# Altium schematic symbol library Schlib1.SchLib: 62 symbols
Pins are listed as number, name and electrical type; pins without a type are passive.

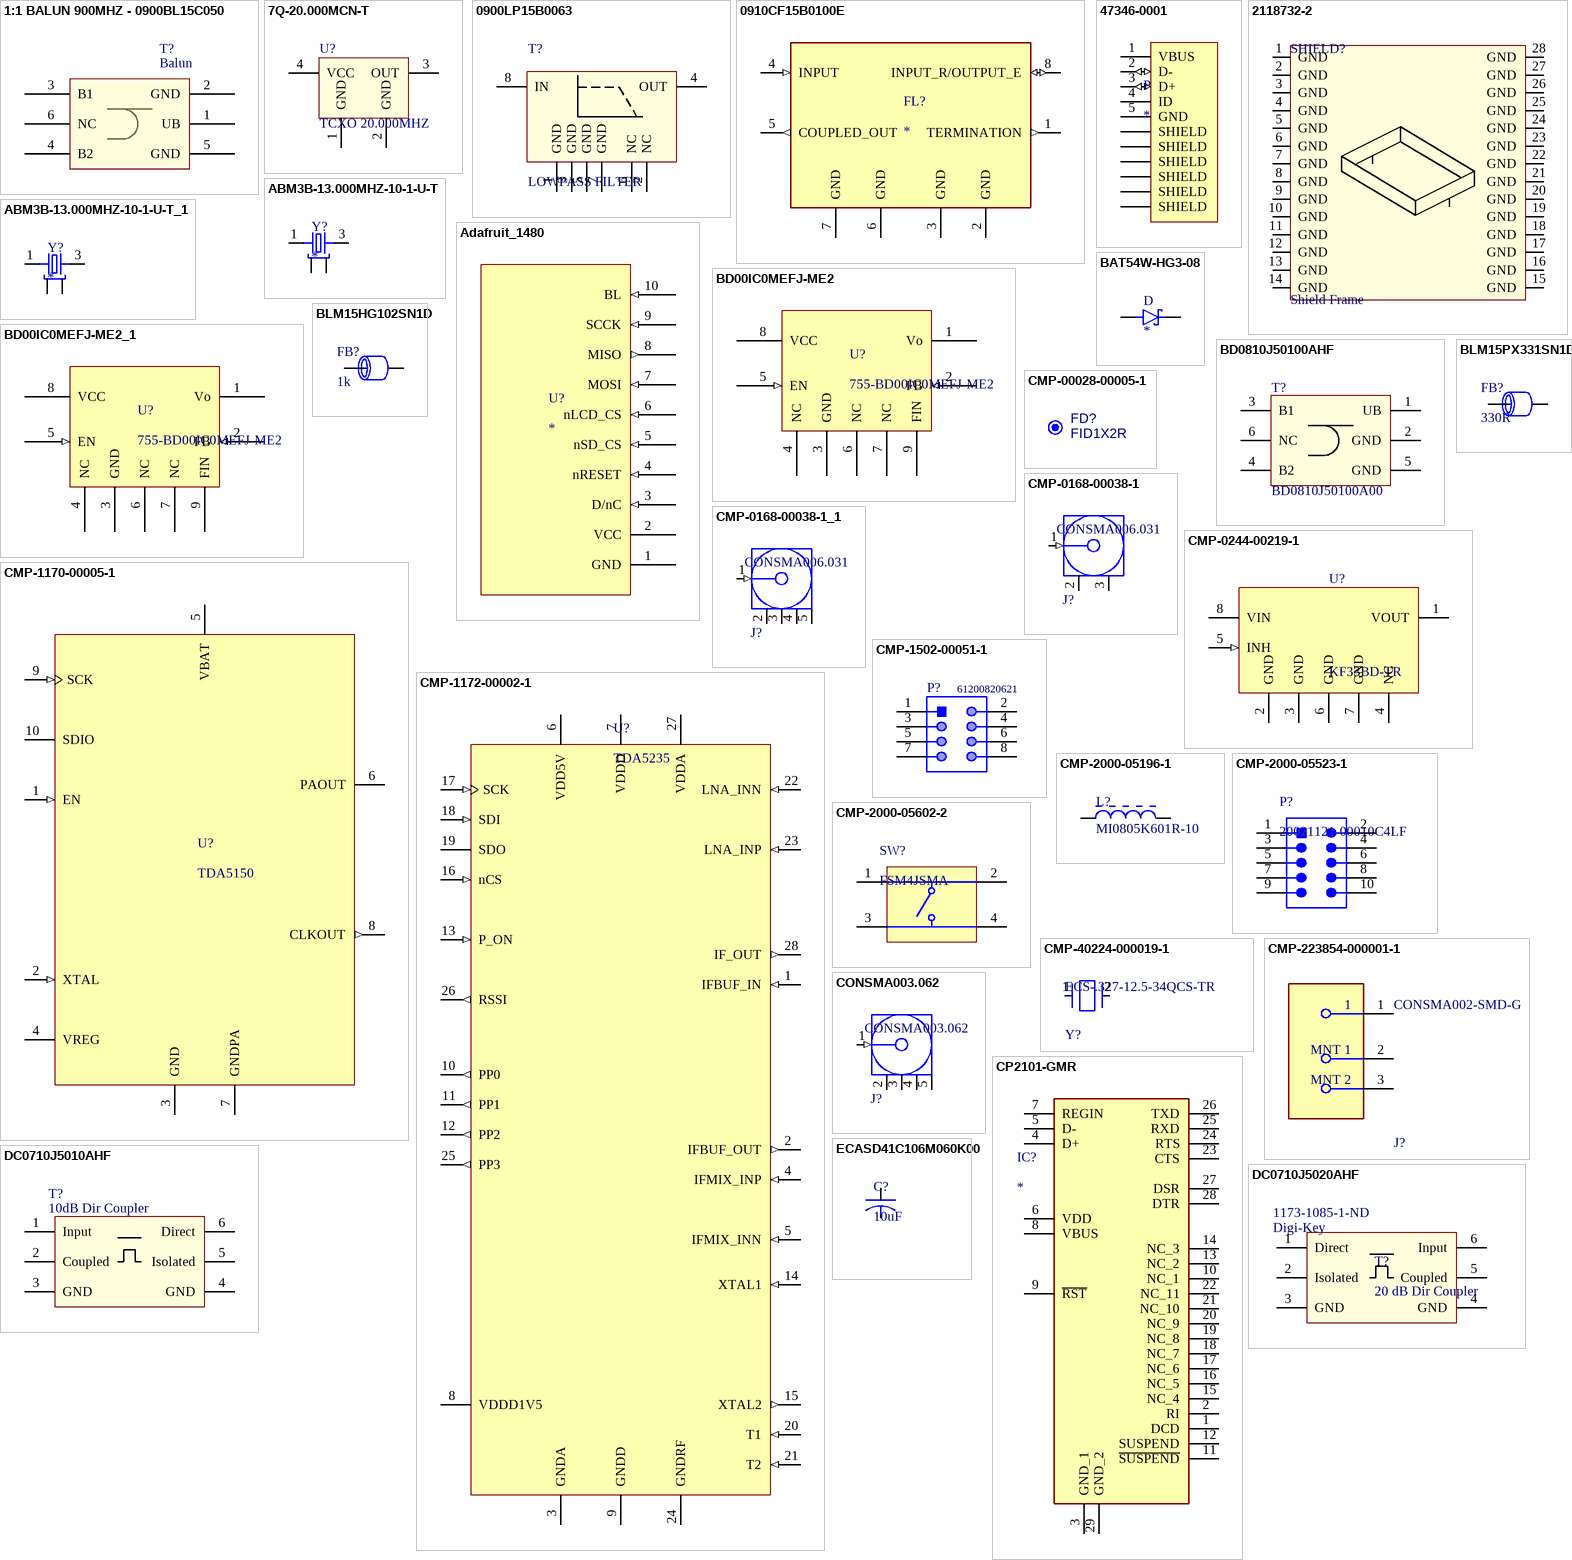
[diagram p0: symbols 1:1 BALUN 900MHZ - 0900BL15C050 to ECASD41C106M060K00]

## 1:1 BALUN 900MHZ - 0900BL15C050
designator T?, comment Balun
1:1 BALUN- 900MHZ 50/50 Ohm; Manufacturer: Johanson Technology Inc; Manufacturer Part Number: 0900BL15C050E; Component_Description: BALUN GSM/DCS/PCS/CDMA 900MHZ; Frequency Range: 800 ~ 1000MHz; Phase Difference: 180° ±10; Insertion Loss (Max): 1.2dB; Return Loss (Min): 9.5dB
footprint JTI-0900BL15C050 (900 MHz Balun 1:1)
pins: 1 UB, 2 GND, 3 B1, 4 B2, 5 GND, 6 NC

## 7Q-20.000MCN-T
designator U?, comment TCXO 20.000MHZ
OSC TCXO 20.000MHZ CLPD SNWV SMD; Manufacturer: Taitien; Manufacturer Part Number: TXEAADSANF-20.000000; Output: Clipped Sine Wave; Voltage - Supply: 2.8 V ~ 3.3 V; Frequency Stability: ±500ppb; Current - Supply (Max): 2mA
footprint 7Q-20.000MCN-T (Footprint not found)
footprint TY_TYPE_2.5x2.0mm (TCXO package Taitien TY type)
pins: 1 GND, 2 GND, 3 OUT, 4 VCC

## 0900LP15B0063
designator T?, comment LOWPASS FILTER
FILTER LOWPASS 863-960MHZ; Manufacturer: Johanson Technology Inc.; Manufacturer Part Number: 0900LP15B0063E
footprint JTI-0900LP15B0063 (900 MHz Low Pass Filter)
pins: 1 GND, 2 NC, 3 GND, 4 OUT, 5 GND, 6 NC, 7 GND, 8 IN

## 0910CF15B0100E
designator FL?
RF Couplers Coupling 10dB 0.86GHz to 0.96GHz 8-Pin T/R; MP: 0910CF15B0100E
footprint FIL_0910CF15B0100E
pins: 1 TERMINATION (out), 2 GND (power), 3 GND (power), 4 INPUT (in), 5 COUPLED_OUT (out), 6 GND (power), 7 GND (power), 8 INPUT_R/OUTPUT_E (io)

## 47346-0001
designator P
USB - micro B USB 2.0 Receptacle Connector 5 Position Surface Mount, Right Angle; MF: Molex; MP: 47346-0001
footprint MOLEX_47346-0001 (Footprint not found)
pins: 1 VBUS (power), 2 D- (io), 3 D+ (io), 4 ID, 5 GND (power), SH1 SHIELD, SH2 SHIELD, SH3 SHIELD, SH4 SHIELD, SH5 SHIELD, SH6 SHIELD

## 2118732-2
designator SHIELD?, comment Shield Frame
RF Shield 51.1 x 38.4 x 6.5; Manufacturer: TE Connectivity AMP Connectors; Manufacturer Part Number: 2118732-2
footprint RF Shield - 50.8 x 38.1 mm (2118732-2)
pins: 1 GND, 2 GND, 3 GND, 4 GND, 5 GND, 6 GND, 7 GND, 8 GND, 9 GND, 10 GND, 11 GND, 12 GND, 13 GND, 14 GND, 15 GND, 16 GND, 17 GND, 18 GND, 19 GND, 20 GND, 21 GND, 22 GND, 23 GND, 24 GND, 25 GND, 26 GND, 27 GND, 28 GND

## ABM3B-13.000MHZ-10-1-U-T
designator Y?
Ceramic SMD Crystal; MP: ABM3B-13.000MHZ-10-1-U-T
footprint OSCCC500X320X110-4N
pins: 1, 2 GND, 3, 4 GND

## ABM3B-13.000MHZ-10-1-U-T_1
designator Y?
Ceramic SMD Crystal; MP: ABM3B-13.000MHZ-10-1-U-T
footprint OSCCC500X320X110-4N
pins: 1, 2 GND, 3, 4 GND

## Adafruit_1480
designator U?
LCD Module Adafruit 1480, SPI 320x240p 2.2"
pins: 1 GND (power), 2 VCC (power), 3 D/nC (in), 4 nRESET (in), 5 nSD_CS (in), 6 nLCD_CS (in), 7 MOSI (in), 8 MISO (out), 9 SCCK (in), 10 BL (in)

## BAT54W-HG3-08
designator D
Schottky Diodes & Rectifiers 30V Zener SKY DIODE SOD-123; MP: BAT54W-HG3-08; MF: Vishay Semiconductors
footprint SOD3715X135N
pins: A, K

## BD00IC0MEFJ-ME2
designator U?, comment 755-BD00IC0MEFJ-ME2
Régulateurs de tension LDO IC Pwr Linear Reg Single Output LDO
footprint HTSOP-J8 (HTSOP, 8-Leads, Body 4.90x3.90mm, Pitch 1.27mm, Thermal Pad 3.20x2.40mm, IPC Medium Density)
pins: 1 Vo (power), 2 FB (in), 3 GND (power), 4 NC (power), 5 EN (in), 6 NC (power), 7 NC (power), 8 VCC (power), 9 FIN (power)

## BD00IC0MEFJ-ME2_1
designator U?, comment 755-BD00IC0MEFJ-ME2
Régulateurs de tension LDO IC Pwr Linear Reg Single Output LDO
footprint HTSOP-J8 (HTSOP, 8-Leads, Body 4.90x3.90mm, Pitch 1.27mm, Thermal Pad 3.20x2.40mm, IPC Medium Density)
pins: 1 Vo (power), 2 FB (in), 3 GND (power), 4 NC (power), 5 EN (in), 6 NC (power), 7 NC (power), 8 VCC (power), 9 FIN (power)

## BD0810J50100AHF
designator T?, comment BD0810J50100A00
XFRMR BALUN RF 800-1000MHZ 0805; Manufacturer: Anaren; Manufacturer Part Number: BD0810J50100AHF; Frequency Range: 800MHz ~ 1GHz; Impedance - Unbalanced/Balanced: 50 / 100 Ohm; Phase Difference: 1°; Insertion Loss (Max): 0.95dB; Return Loss (Min): 13dB
footprint BD0810J50100AHF (RF Balun 800MHz ~ 1GHz 50 / 100 Ohm 0805)
pins: 1 UB, 2 GND, 3 B1, 4 B2, 5 GND, 6 NC

## BLM15HG102SN1D
designator FB?, comment 1k
FERRITE BEAD 1 KOHM 0402 1LN; Manufacturer: Murata Electronics North America; Manufacturer Part Number: BLM15HG102SN1D; Filter Type: Signal Line; Number of Lines: 1; Impedance @ Frequency: 1 kOhm @ 100MHz; Current Rating (Max): 250mA; DC Resistance (DCR) (Max): 1.1 Ohm
footprint L0402-RF
pins: 1, 2

## BLM15PX331SN1D
designator FB?, comment 330R
FERRITE BEAD 330 OHM 0402 1LN; Manufacturer: Murata Electronics North America; Manufacturer Part Number: BLM15PX331SN1D; Filter Type: Power Line; Current Rating (Max): 1.2A; DC Resistance (DCR) (Max): 150 mOhm
footprint FB0402-RF (Ferrite Bead)
pins: 1, 2

## CMP-00028-00005-1
designator FD?, comment FID1X2R  (no BOM)
Fiducial - Round 1x2mm
footprint FID1X2R (Fiducial - Round 1x2mm)
footprint FID1X2R (Fiducial - Round 1x2mm)

## CMP-0168-00038-1
designator J?, comment CONSMA006.031
SMA Female Edge Multi-Mount Connector for 0.031" Thick Board; PCB_Layout: Pads complies with manufacturer's recommendation.
footprint CON-SMA-MM031 (Connector, SMA Female Edge Multi-Mount for 0.031" Thick Board, 5-Lead, Body Dia. 7.9mm)
footprint FP-U_FL-R-SMT-1_10-MFG
pins: 1 Signal (in) "Signal Pin", 2 GND (power), 3 GND (power)

## CMP-0168-00038-1_1
designator J?, comment CONSMA006.031
SMA Female Edge Multi-Mount Connector for 0.031" Thick Board; PCB_Layout: Pads complies with manufacturer's recommendation.
footprint CON-SMA-MM031 (Connector, SMA Female Edge Multi-Mount for 0.031" Thick Board, 5-Lead, Body Dia. 7.9mm)
pins: 1 Signal (in) "Signal Pin", 2 GND (power), 3 GND (power), 4 GND (power), 5 GND (power)

## CMP-0244-00219-1
designator U?, comment KF33BD-TR
Very Low Drop Voltage Regulators with Inhibit, 3.3V, 8-Pin SO, Tape and Reel
footprint SO8_L (SOIC, 8-Leads, Body 4.9x3.9mm, Pitch 1.27mm, IPC High Density)
footprint SO8_N (SOIC, 8-Leads, Body 4.9x3.9mm, Pitch 1.27mm, IPC Medium Density)
footprint SO8_M (SOIC, 8-Leads, Body 4.9x3.9mm, Pitch 1.27mm, IPC Low Density)
pins: 1 VOUT (power), 2 GND (power), 3 GND (power), 4 NC, 5 INH (in), 6 GND (power), 7 GND (power), 8 VIN (power)

## CMP-1170-00005-1
designator U?, comment TDA5150
Multichannel / Multiband Transmitter, -40 to 85 degC, PG-TSSOP-10, Green; Manufacturer: Infineon; Transmit Power (at 3V): 5 dBm, 8 dBm, 10 dBm; Modulation Type: ASK / FSK; Group: SmartLEWIS TX to Multi-Channel Transmitter; Green: yes; Frequency Band: 315 MHz, 434 MHz, 868 MHz, 915 MHz
footprint INF-PG-TSSOP-10_N (SOP, 10-Leads, Body 3x3 mm, Pitch 0.5 mm, IPC Medium Density)
footprint INF-PG-TSSOP-10_M (SOP, 10-Leads, Body 3x3 mm, Pitch 0.5 mm, IPC Low Density)
footprint INF-PG-TSSOP-10_L (SOP, 10-Leads, Body 3x3 mm, Pitch 0.5 mm, IPC High Density)
pins: 1 EN (in) "Clock 3-wire bus", 2 XTAL (in) "Crystal Oscillator (Analog input)", 3 GND (power) "Power supply ground", 4 VREG (power) "Voltage Regulator output", 5 VBAT (power) "Power supply (+)", 6 PAOUT (oc) "RF Power  Amplifier Output  (open drain)", 7 GNDPA (power) "RF Power  Amplifier Ground return", 8 CLKOUT (out) "Programmable Divided Clock", 9 SCK (in) "Clock 3-wire bus", 10 SDIO (hiz) "Data 3-wire bus"

## CMP-1172-00002-1
designator U?, comment TDA5235
Enhanced Sensitivity Double-Configuration Receiver with Digital Baseband Processing, -40 to 105 degC, PG-TSSOP-28, Green; Manufacturer: Infineon; Digital Baseband / Autonomous RX: yes; Frequency Band: 315 MHz, 434 MHz, 868 MHz, 915 MHz; Modulation Type: ASK / FSK; Group: SmartLEWIS RX+ to High Sensitivity Receiver with Digital Baseband Processing; Channel Requirements per Band: Single-Channel
footprint INF-PG-TSSOP-28_L (SOP, 28-Leads, Body 9.7x4.4 mm, Pitch 0.65 mm, IPC High Density)
footprint INF-PG-TSSOP-28_N (SOP, 28-Leads, Body 9.7x4.4 mm, Pitch 0.65 mm, IPC Medium Density)
footprint INF-PG-TSSOP-28_M (SOP, 28-Leads, Body 9.7x4.4 mm, Pitch 0.65 mm, IPC Low Density)
pins: 1 IFBUF_IN (in) "Analog input IF Buffer input Note: Input is biased at VDDA/2", 2 IFBUF_OUT (out) "Analog output IF Buffer output", 3 GNDA (power) "Analog ground", 4 IFMIX_INP (in) "Analog input + IF mixer input Note: Input is biased at VDDA/2", 5 IFMIX_INN (in) "Analog input. - IF mixer input", 6 VDD5V (power) "Analog input 5 Volt supply input", 7 VDDD (power) "Analog input digital supply input", 8 VDDD1V5 (power) "Analog output 1.5 Volt voltage regulator", 9 GNDD (power) "Digital ground", 10 PP0 (out) "Digital output CLK_OUT, RX_RUN, NINT, LOW, HIGH, DATA and DATA_MATCHFIL are programmable via a SFR (Special Function Register), default = CLK_OUT", 11 PP1 (out) "Digital output CLK_OUT, RX_RUN, NINT, LOW, HIGH, DATA and DATA_MATCHFIL are programmable via a SFR, default = DATA", 12 PP2 (out) "Digital output CLK_OUT, RX_RUN, NINT, LOW, HIGH, DATA and DATA_MATCHFIL are programmable via a SFR, default = NINT", 13 P_ON (in) "Digital input power-on reset", 14 XTAL1 (in) "Analog input crystal oscillator input", 15 XTAL2 (out) "Analog output crystal oscillator output", 16 nCS (in) "Digital input SPI enable", 17 SCK (in) "Digital input SPI clock", 18 SDI (in) "Digital input SPI data in", 19 SDO (hiz) "Digital output SPI data out", 20 T1 (in) "Digital input, connect to Digital Ground", 21 T2 (in) "Digital input, connect to Digital Ground", 22 LNA_INN (in) "Analog input - RF input", 23 LNA_INP (in) "Analog input + RF input", 24 GNDRF (power) "RF analog ground", 25 PP3 (out) "Digital output RX_RUN, NINT, LOW, HIGH, DATA and DATA_MATCHFIL are programmable via a SFR, default = RX_RUN", 26 RSSI (out) "Analog output analog RSSI output/ analog test pin ANA_TST", 27 VDDA (power) "Analog input Analog supply", 28 IF_OUT (out) "Analog output IF output"

## CMP-1502-00051-1
designator P?, comment 61200820621
Male Box Header WR-BHD, SMT, Vertical, pitch 2.54 mm, 8 pins; Manufacturer: Wurth Elektronik; Withstanding Voltage: 500VAC; Pin Number: 8; Pitch: 2.54mm; Contact Resistance: 20mOhm; Working Voltage: 250VAC
footprint 61200820621 (8 pins, SMT, straight, gold plating)
pins: 1, 2, 3, 4, 5, 6, 7, 8

## CMP-2000-05196-1
designator L?, comment MI0805K601R-10
Chip Bead for Power Filtering, 1500 mA, 600 Ohm, -40 to 125 degC, 0805 (2012 Metric), RoHS, Tape and Reel; Manufacturer: Laird; Filter Type: PowerLine; Current Rating (Max): 1.5A; Catalog Drawings: (HI,HZ,LI,MI)0805Series_1.10mmMax.Height; Impedance @ Frequency: 600Ohm@100MHz; Number of Lines: 1; DC Resistance (DCR) (Max): 100mOhm; Other Names: 240-2390-1; Kits: 240-2227-ND-KITEMIFERRITEBEADCHIPSMD; Online Catalog: MISeries
footprint LIRD-MI0805K601R-10-2_V (Chip Bead, 2-Leads, Body 2.2 x1.45 mm)
pins: 1, 2

## CMP-2000-05523-1
designator P?, comment 20021121-00010C4LF
Male Header, Pitch 1.27 mm, 2 x 5 Position, Height 4.55 mm, -40 to 85 degC, RoHS, Tape and Reel; Brand: FCI; Mating Post Length: 3.05mm; Voltage Rating: 125V; Contact resistance Max: 30MOhm; Number of Positions: 10; Pitch: 1.27mm; Current Rating: 1A; Stack Height: 3mm; Mounting Angle: Vertical; Package Version: Rev. J, 03/2013
footprint HDR2X5_SMT (Header, 10-Leads, Body 3.43x6.35mm, Pitch 1.27mm)
pins: 1, 2, 3, 4, 5, 6, 7, 8, 9, 10

## CMP-2000-05602-2
designator SW?, comment FSM4JSMA
Swicth, SPST, 24 V, -35 to 85 degC, 4-Pin SMD, RoHS, Tape and Reel; Manufacturer: TE Connectivity; Switch Travel: 0.25mm; Mechanical Life: 100000Cycles; Contact Current Rating: 50mA; Operating Force: 1.57N; Actuator Material: Polyamide; Contact Resistance: 100mOhm; Voltage Rating: 24V; Illumination Type: Illuminated; Actuator Length: 0.055inch; Max Voltage Rating (DC): 12V; Case\/Package: SMD/SMT
footprint RKB2SJK250SMTRLFS
pins: 1, 2, 3, 4

## CMP-40224-000019-1
designator Y?, comment ECS-.327-12.5-34QCS-TR
CRYSTAL 32.768KHZ 12.5PF SMD; ESR (Equivalent Series Resistance): 80kR; Frequency Tolerance: 10ppm
footprint FP-ECX-34Q-MFG
pins: 1 In/Out (io), 2 Out/In (io)

## CMP-223854-000001-1
designator J?, comment CONSMA002-SMD-G
CONN SMA RCPT R/A 50 OHM SMD; Manufacturer: Linx Technologies; Impedance: 50Ω; Is Female: yes; Number Of Contacts: 1; Conn Orientation: Right Angle; Shielding: true; Voltage Rating: 1000V; Standoff Height: 0mm; Frequency: 18GHz; Dielectric Material: PTFE
footprint FP-CONSMA002-SMD-G-MFG
pins: 1, 2 MNT 1, 3 MNT 2

## CONSMA003.062
designator J?
SMA Female Edge Multi-Mount Connector for 0.062" Thick Board; PCB_Layout: Pads complies with manufacturer's recommendation.
footprint CON-SMA-MM031 (Connector, SMA Female Edge Multi-Mount for 0.031" Thick Board, 5-Lead, Body Dia. 7.9mm)
footprint LINX_CONSMA003.062
pins: 1 Signal (in) "Signal Pin", 2 GND (power), 3 GND (power), 4 GND (power), 5 GND (power)

## CP2101-GMR
designator IC?
Integrated Circuit; Manufacturer_Name: Silicon Labs; Manufacturer_Part_Number: CP2101-GMR; Description: I/O Controller Interface IC USB to UART Bridge QFN28
footprint QFN50P500X500X100-29N-D
pins: 1 DCD, 2 RI, 3 GND_1, 4 D+, 5 D-, 6 VDD, 7 REGIN, 8 VBUS, 9 ~{RST}, 10 NC_1, 11 ~{SUSPEND}, 12 SUSPEND, 13 NC_2, 14 NC_3, 15 NC_4, 16 NC_5, 17 NC_6, 18 NC_7, 19 NC_8, 20 NC_9, 21 NC_10, 22 NC_11, 23 CTS, 24 RTS, 25 RXD, 26 TXD, 27 DSR, 28 DTR, 29 GND_2

## DC0710J5010AHF
designator T?, comment 10dB Dir Coupler
Directional Coupler; Manufacturer: Anaren; Manufacturer Part Number: DC0710J5010AHF; Coupler Type: Standard; Frequency: 700MHz ~ 1GHz; Coupling Factor: 10.9dB; Insertion Loss: 0.21dB; Power - Max: 2W; Return Loss: 17.5dB
footprint DC0710J5010AHF (Directional Coupler)
pins: 1 Input, 2 Coupled, 3 GND, 4 GND, 5 Isolated, 6 Direct

## DC0710J5020AHF
designator T?, comment 20 dB Dir Coupler  Supplier 1: Digi-Key  Supplier Part Number 1: 1173-1085-1-ND
COUPLER 20DB 700-1000MHZ 0805; Manufacturer: Anaren; Manufacturer Part Number: DC0710J5020AHF; Frequency: 700MHz; Insertion Loss: 0.22dB; Max Power Dissipation: 2W; Return Loss: 21.41dB
footprint DC0710J5010AHF (Directional Coupler)
pins: 1 Direct, 2 Isolated, 3 GND, 4 GND, 5 Coupled, 6 Input

## ECASD41C106M060K00
designator C?, comment 10uF
CAP POLYMER 10UF 20% 16V SMD; Manufacturer: Murata; Manufacturer Part Number: ECASD41C106M060K00; Product Training Modules: Polymer Aluminum Electrolytic Capacitors Using Murata's Polymer Aluminum Capacitors to Replace Tantalum; Catalog Drawings: ECAS Series End_D4 ECAS Series Side; Featured Product: ECAS Series Polymer Aluminum Electrolytic Capacitors; EDA / CAD Models: Download from Accelerated Designs; Capacitance: 10µF; ESR (Equivalent Series Resistance): 60 mOhm @ 100kHz; Lifetime @ Temp.: 1000 Hrs @ 105°C; Polarization: Polar; Ripple Current: 1A; Surface Mount Land Size: 0.287" L x 0.169" W (7.30mm x 4.30mm); Online Catalog: ECAS Series; Other Names: 490-5482-2
footprint 2917(7343) (Chip Capacitor, 2-Leads, Body 7,30x4,30mm, IPC Medium Density)
pins: 1, 2

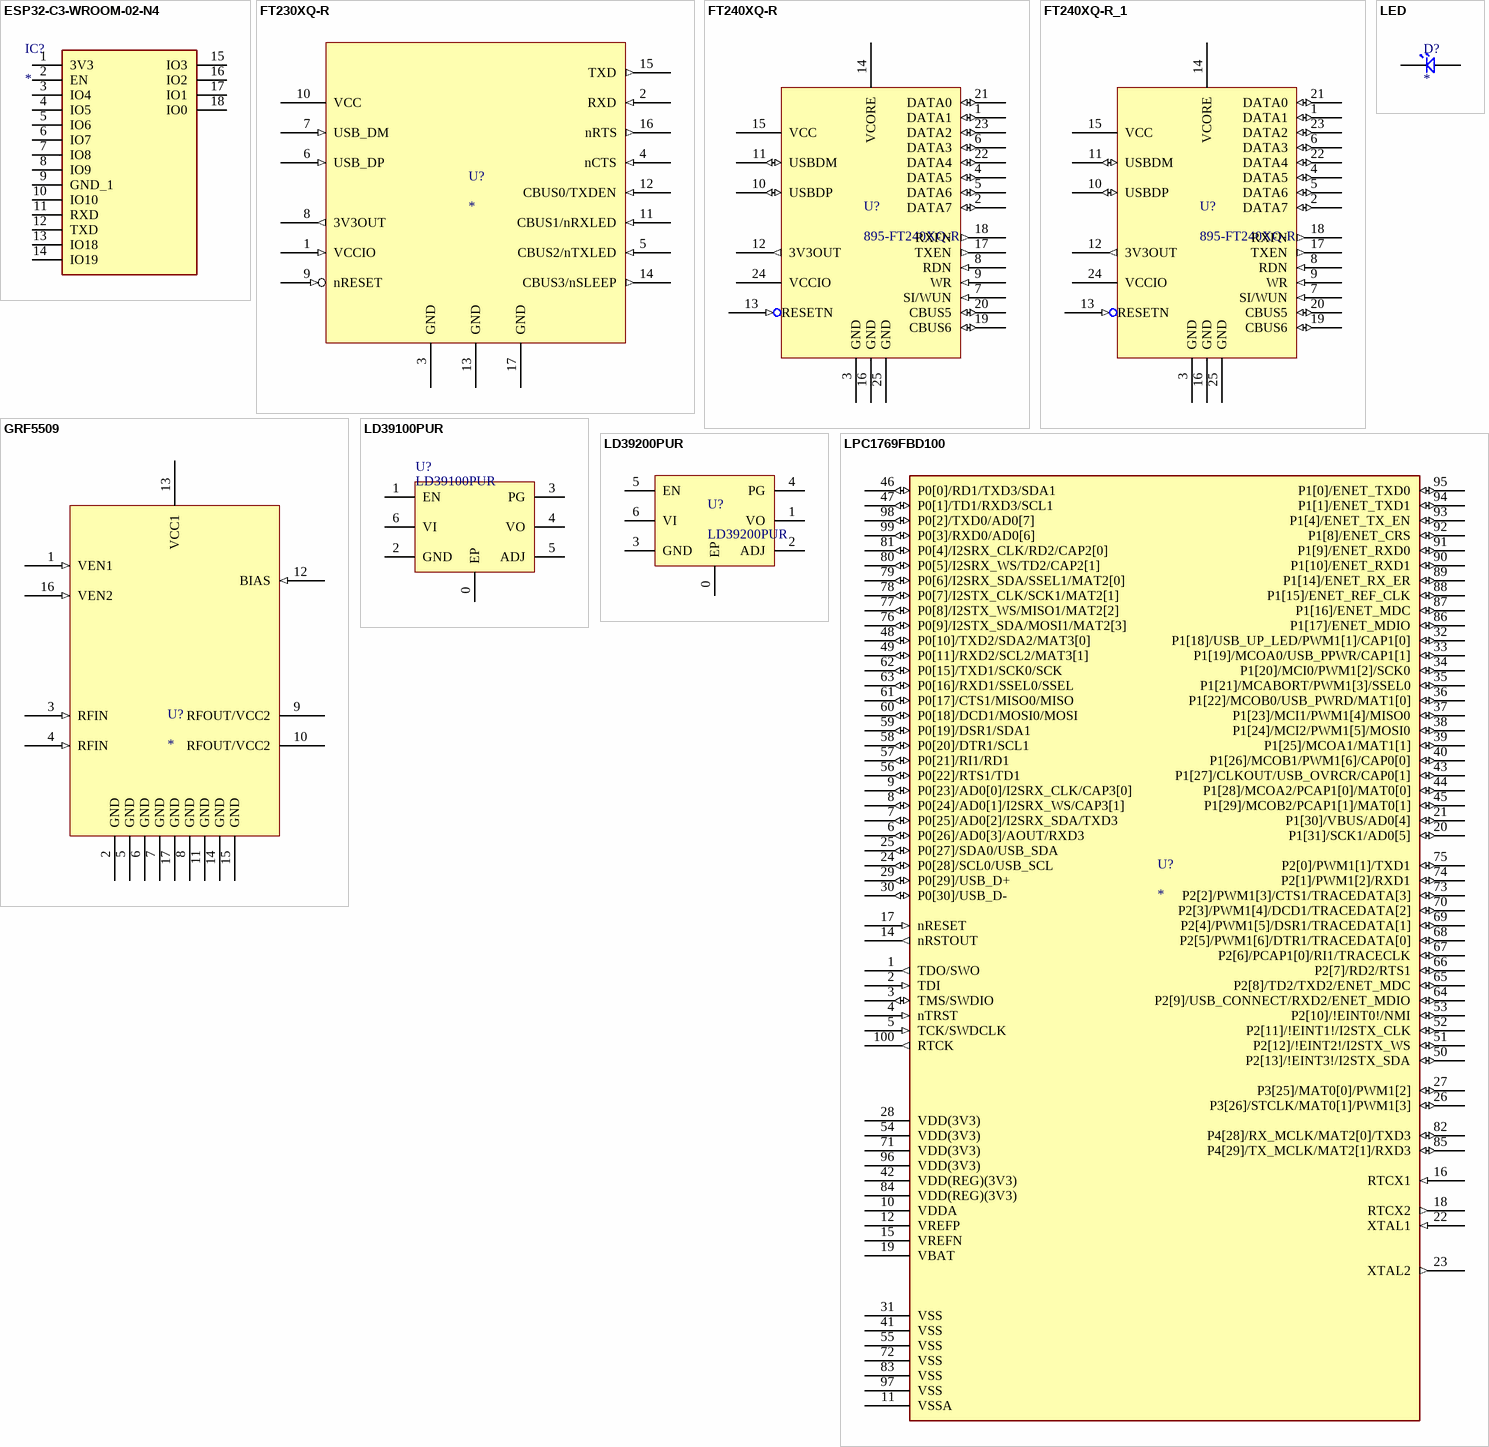
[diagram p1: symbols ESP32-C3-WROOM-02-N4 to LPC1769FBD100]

## ESP32-C3-WROOM-02-N4
designator IC?
Integrated Circuit; Manufacturer_Name: Espressif Systems; Manufacturer_Part_Number: ESP32-C3-WROOM-02-N4
footprint ESP32C3WROOM02N4
pins: 1 3V3, 2 EN, 3 IO4, 4 IO5, 5 IO6, 6 IO7, 7 IO8, 8 IO9, 9 GND_1, 10 IO10, 11 RXD, 12 TXD, 13 IO18, 14 IO19, 15 IO3, 16 IO2, 17 IO1, 18 IO0

## FT230XQ-R
designator U?
USB/UART interface
footprint FP-QFN-16-MFG
pins: 1 VCCIO (in), 2 RXD (in), 3 GND (power), 4 nCTS (in), 5 CBUS2/nTXLED (in), 6 USB_DP (in), 7 USB_DM (in), 8 3V3OUT (out), 9 nRESET (in), 10 VCC (power), 11 CBUS1/nRXLED (in), 12 CBUS0/TXDEN (in), 13 GND (power), 14 CBUS3/nSLEEP (out), 15 TXD (out), 16 nRTS (out), 17 GND (power)

## FT240XQ-R
designator U?, comment 895-FT240XQ-R
Circuit intégré d'interface USB USB to Parallel FIFO IC QFN-24
footprint QFN-24 package - WQFN(X424) pad 114x114 (QFN, 24-Leads, Body 4.00x4.00mm, Pitch 0.50mm, Thermal Pad 2.68x2.68mm, IPC Medium Density)
pins: 1 DATA1 (io), 2 DATA7 (io), 3 GND (power), 4 DATA5 (io), 5 DATA6 (io), 6 DATA3 (io), 7 SI/WUN (in), 8 RDN (in), 9 WR (in), 10 USBDP (io), 11 USBDM (io), 12 3V3OUT (out), 13 RESETN (in), 14 VCORE (power), 15 VCC (power), 16 GND (power), 17 TXEN (out), 18 RXFN (out), 19 CBUS6 (io), 20 CBUS5 (io), 21 DATA0 (io), 22 DATA4 (io), 23 DATA2 (io), 24 VCCIO (power), 25 GND (power)

## FT240XQ-R_1
designator U?, comment 895-FT240XQ-R
Circuit intégré d'interface USB USB to Parallel FIFO IC QFN-24
footprint QFN-24 package - WQFN(X424) pad 114x114 (QFN, 24-Leads, Body 4.00x4.00mm, Pitch 0.50mm, Thermal Pad 2.68x2.68mm, IPC Medium Density)
pins: 1 DATA1 (io), 2 DATA7 (io), 3 GND (power), 4 DATA5 (io), 5 DATA6 (io), 6 DATA3 (io), 7 SI/WUN (in), 8 RDN (in), 9 WR (in), 10 USBDP (io), 11 USBDM (io), 12 3V3OUT (out), 13 RESETN (in), 14 VCORE (power), 15 VCC (power), 16 GND (power), 17 TXEN (out), 18 RXFN (out), 19 CBUS6 (io), 20 CBUS5 (io), 21 DATA0 (io), 22 DATA4 (io), 23 DATA2 (io), 24 VCCIO (power), 25 GND (power)

## GRF5509
designator U?
pins: 1 VEN1 (in), 2 GND (power), 3 RFIN (in), 4 RFIN (in), 5 GND (power), 6 GND (power), 7 GND (power), 8 GND (power), 9 RFOUT/VCC2 (oc), 10 RFOUT/VCC2 (oc), 11 GND (power), 12 BIAS (in), 13 VCC1 (power), 14 GND (power), 15 GND (power), 16 VEN2 (in), 17 GND (power) "PKG BASE"

## LD39100PUR
designator U?
IC REG LDO ADJ 1A 6DFN; Manufacturer: STMicroelectronics; Regulator Topology: Positive Adjustable; Voltage - Output: 0.8 V ~ 4.5 V; Voltage - Dropout (Typical): 0.2V @ 1A; Number of Regulators: 1; Voltage - Input: 1.5 V ~ 5.5 V; Exact Component Match: yes
footprint LD39100PUR (1 A, low quiescent current, low-noise voltage regulator)
pins: 0 EP, 1 EN, 2 GND, 3 PG, 4 VO, 5 ADJ, 6 VI

## LD39200PUR
designator U?
Manufacturer: STMicroelectronics; Capacitance: 10uF; Tolerance: 20%; Dielectric: X6S; Voltage Rating (DC): 10V
footprint LD39200PUR (2 A, low quiescent current, low-noise voltage regulator)
pins: 0 EP, 1 VO, 2 ADJ, 3 GND, 4 PG, 5 EN, 6 VI

## LED
designator D?
footprint LTST-C170KRKT_V (SMD, 2-Leads, Body 2x1.25mm)
pins: A, K

## LPC1769FBD100
designator U?
ARMÂ® CortexÂ®-M3 LPC17xx Microcontroller IC 32-Bit 120MHz 512KB (512K x 8) FLASH 100-LQFP (14x14); MP: LPC1769FBD100; MF: NXP Semiconductors
footprint SOT407-1
pins: 1 TDO/SWO (out), 2 TDI (in), 3 TMS/SWDIO (io), 4 nTRST (in), 5 TCK/SWDCLK (in), 6 P0[26]/AD0[3]/AOUT/RXD3 (io), 7 P0[25]/AD0[2]/I2SRX_SDA/TXD3 (io), 8 P0[24]/AD0[1]/I2SRX_WS/CAP3[1] (io), 9 P0[23]/AD0[0]/I2SRX_CLK/CAP3[0] (io), 10 VDDA (power), 11 VSSA (power), 12 VREFP (power), 14 nRSTOUT (out), 15 VREFN (power), 16 RTCX1 (in), 17 nRESET (in), 18 RTCX2 (out), 19 VBAT (power), 20 P1[31]/SCK1/AD0[5] (io), 21 P1[30]/VBUS/AD0[4] (io), 22 XTAL1 (in), 23 XTAL2 (out), 24 P0[28]/SCL0/USB_SCL (io), 25 P0[27]/SDA0/USB_SDA (io), 26 P3[26]/STCLK/MAT0[1]/PWM1[3] (io), 27 P3[25]/MAT0[0]/PWM1[2] (io), 28 VDD(3V3) (power), 29 P0[29]/USB_D+ (io), 30 P0[30]/USB_D- (io), 31 VSS (power), 32 P1[18]/USB_UP_LED/PWM1[1]/CAP1[0] (io), 33 P1[19]/MCOA0/USB_PPWR/CAP1[1] (io), 34 P1[20]/MCI0/PWM1[2]/SCK0 (io), 35 P1[21]/MCABORT/PWM1[3]/SSEL0 (io), 36 P1[22]/MCOB0/USB_PWRD/MAT1[0] (io), 37 P1[23]/MCI1/PWM1[4]/MISO0 (io), 38 P1[24]/MCI2/PWM1[5]/MOSI0 (io), 39 P1[25]/MCOA1/MAT1[1] (io), 40 P1[26]/MCOB1/PWM1[6]/CAP0[0] (io), 41 VSS (power), 42 VDD(REG)(3V3) (power), 43 P1[27]/CLKOUT/USB_OVRCR/CAP0[1] (io), 44 P1[28]/MCOA2/PCAP1[0]/MAT0[0] (io), 45 P1[29]/MCOB2/PCAP1[1]/MAT0[1] (io), 46 P0[0]/RD1/TXD3/SDA1 (io), 47 P0[1]/TD1/RXD3/SCL1 (io), 48 P0[10]/TXD2/SDA2/MAT3[0] (io), 49 P0[11]/RXD2/SCL2/MAT3[1] (io), 50 P2[13]/!EINT3!/I2STX_SDA (io), 51 P2[12]/!EINT2!/I2STX_WS (io), 52 P2[11]/!EINT1!/I2STX_CLK (io), 53 P2[10]/!EINT0!/NMI (io), 54 VDD(3V3) (power), 55 VSS (power), 56 P0[22]/RTS1/TD1 (io), 57 P0[21]/RI1/RD1 (io), 58 P0[20]/DTR1/SCL1 (io), 59 P0[19]/DSR1/SDA1 (io), 60 P0[18]/DCD1/MOSI0/MOSI (io), 61 P0[17]/CTS1/MISO0/MISO (io), 62 P0[15]/TXD1/SCK0/SCK (io), 63 P0[16]/RXD1/SSEL0/SSEL (io), 64 P2[9]/USB_CONNECT/RXD2/ENET_MDIO (io), 65 P2[8]/TD2/TXD2/ENET_MDC (io), 66 P2[7]/RD2/RTS1 (io), 67 P2[6]/PCAP1[0]/RI1/TRACECLK (io), 68 P2[5]/PWM1[6]/DTR1/TRACEDATA[0] (io), 69 P2[4]/PWM1[5]/DSR1/TRACEDATA[1] (io), 70 P2[3]/PWM1[4]/DCD1/TRACEDATA[2] (io), 71 VDD(3V3) (power), 72 VSS (power), 73 P2[2]/PWM1[3]/CTS1/TRACEDATA[3] (io), 74 P2[1]/PWM1[2]/RXD1 (io), 75 P2[0]/PWM1[1]/TXD1 (io), 76 P0[9]/I2STX_SDA/MOSI1/MAT2[3] (io), 77 P0[8]/I2STX_WS/MISO1/MAT2[2] (io), 78 P0[7]/I2STX_CLK/SCK1/MAT2[1] (io), 79 P0[6]/I2SRX_SDA/SSEL1/MAT2[0] (io), 80 P0[5]/I2SRX_WS/TD2/CAP2[1] (io), 81 P0[4]/I2SRX_CLK/RD2/CAP2[0] (io), 82 P4[28]/RX_MCLK/MAT2[0]/TXD3 (io), 83 VSS (power), 84 VDD(REG)(3V3) (power), 85 P4[29]/TX_MCLK/MAT2[1]/RXD3 (io), 86 P1[17]/ENET_MDIO (io), 87 P1[16]/ENET_MDC (io), 88 P1[15]/ENET_REF_CLK (io), 89 P1[14]/ENET_RX_ER (io), 90 P1[10]/ENET_RXD1 (io), 91 P1[9]/ENET_RXD0 (io), 92 P1[8]/ENET_CRS (io), 93 P1[4]/ENET_TX_EN (io), 94 P1[1]/ENET_TXD1 (io), 95 P1[0]/ENET_TXD0 (io), 96 VDD(3V3) (power), 97 VSS (power), 98 P0[2]/TXD0/AD0[7] (io), 99 P0[3]/RXD0/AD0[6] (io), 100 RTCK (out)

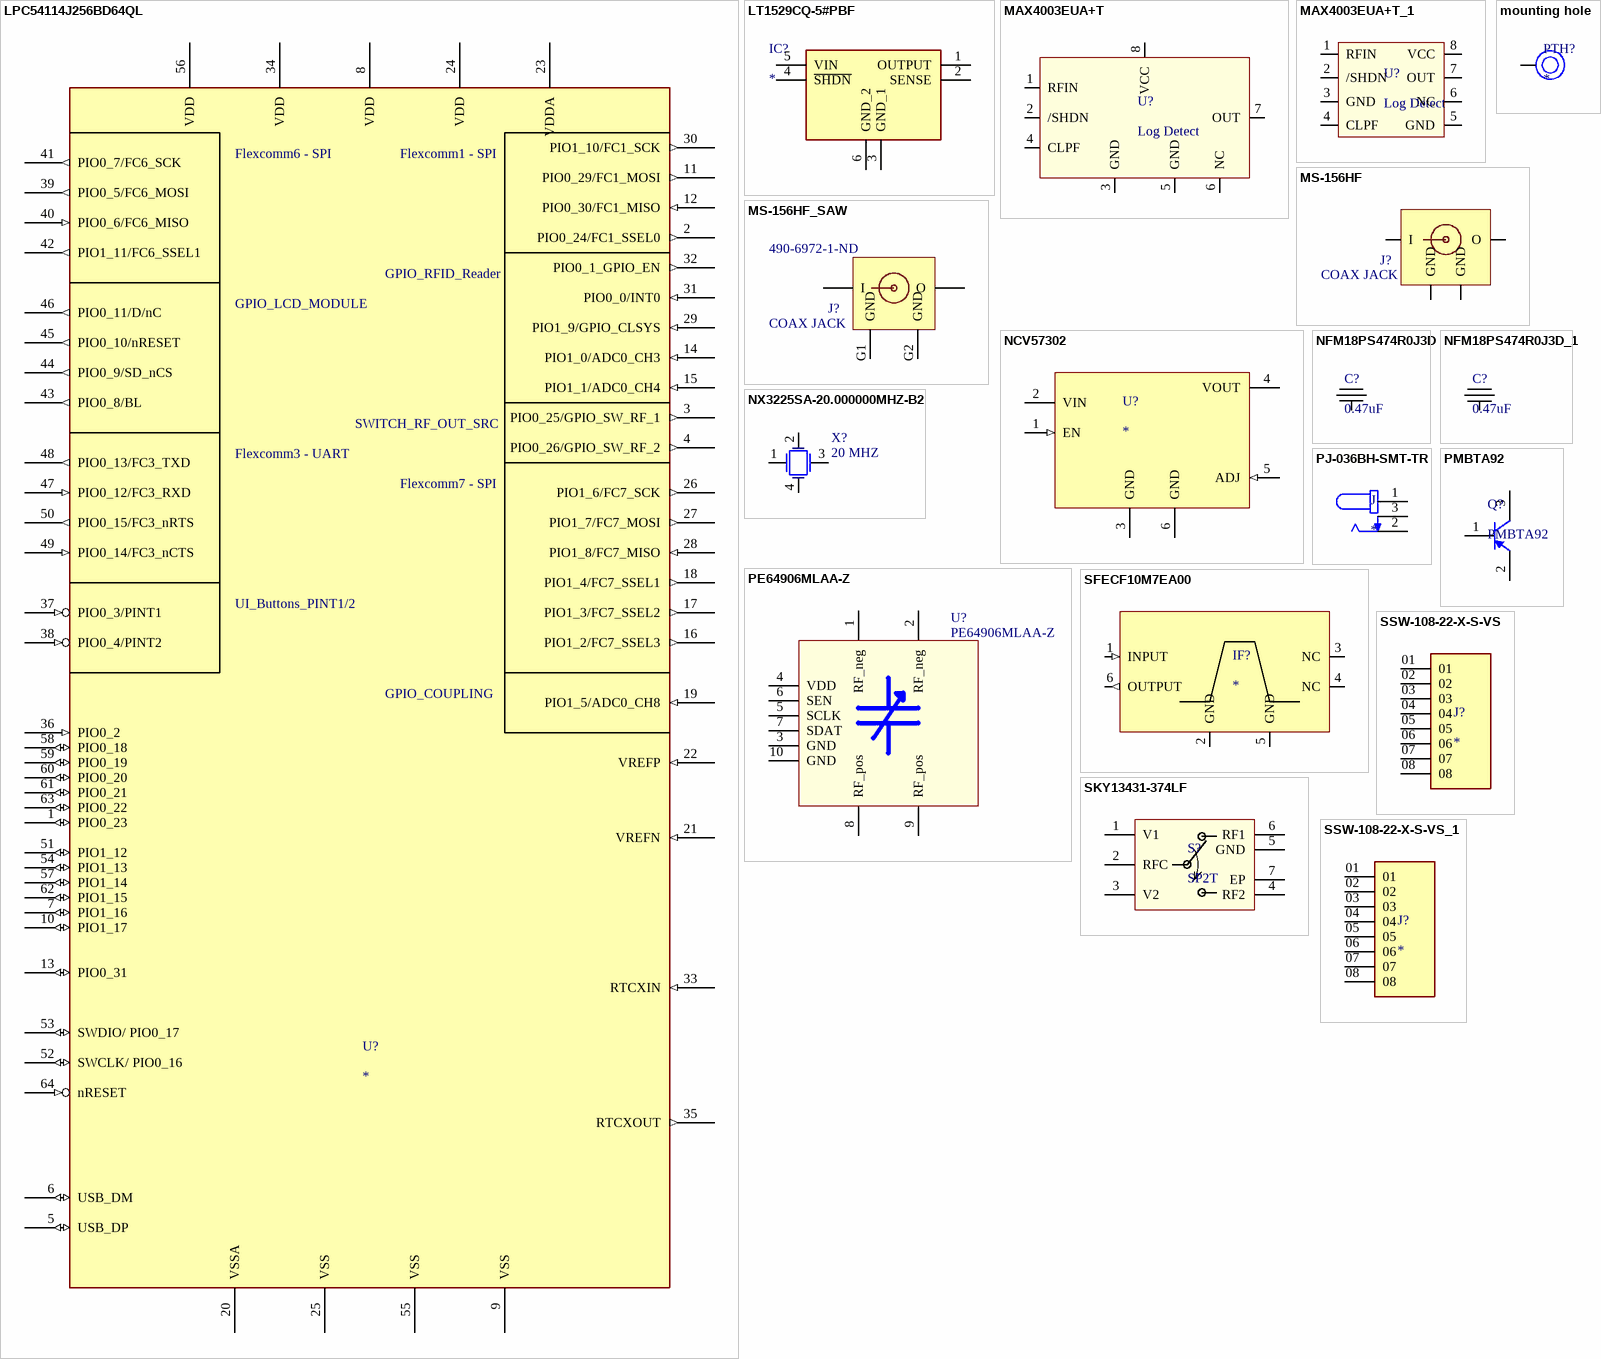
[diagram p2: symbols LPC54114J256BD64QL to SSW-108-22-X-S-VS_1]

## LPC54114J256BD64QL
designator U?
pins: 1 PIO0_23 (io), 2 PIO0_24/FC1_SSEL0 (out), 3 PIO0_25/GPIO_SW_RF_1 (out), 4 PIO0_26/GPIO_SW_RF_2 (out), 5 USB_DP (io), 6 USB_DM (io), 7 PIO1_16 (io), 8 VDD (power), 9 VSS (power), 10 PIO1_17 (io), 11 PIO0_29/FC1_MOSI (out), 12 PIO0_30/FC1_MISO (in), 13 PIO0_31 (io), 14 PIO1_0/ADC0_CH3 (in), 15 PIO1_1/ADC0_CH4 (in), 16 PIO1_2/FC7_SSEL3 (out), 17 PIO1_3/FC7_SSEL2 (out), 18 PIO1_4/FC7_SSEL1 (out), 19 PIO1_5/ADC0_CH8 (in), 20 VSSA (power), 21 VREFN (in), 22 VREFP (in), 23 VDDA (power), 24 VDD (power), 25 VSS (power), 26 PIO1_6/FC7_SCK (out), 27 PIO1_7/FC7_MOSI (out), 28 PIO1_8/FC7_MISO (in), 29 PIO1_9/GPIO_CLSYS (in), 30 PIO1_10/FC1_SCK (out), 31 PIO0_0/INT0 (in), 32 PIO0_1_GPIO_EN (out), 33 RTCXIN (in), 34 VDD (power), 35 RTCXOUT (out), 36 PIO0_2 (in), 37 PIO0_3/PINT1 (in), 38 PIO0_4/PINT2 (in), 39 PIO0_5/FC6_MOSI (out), 40 PIO0_6/FC6_MISO (in), 41 PIO0_7/FC6_SCK (out), 42 PIO1_11/FC6_SSEL1 (out), 43 PIO0_8/BL (out), 44 PIO0_9/SD_nCS (out), 45 PIO0_10/nRESET (out), 46 PIO0_11/D/nC (out), 47 PIO0_12/FC3_RXD (in), 48 PIO0_13/FC3_TXD (out), 49 PIO0_14/FC3_nCTS (in), 50 PIO0_15/FC3_nRTS (out), 51 PIO1_12 (io), 52 SWCLK/ PIO0_16 (io), 53 SWDIO/ PIO0_17 (io), 54 PIO1_13 (io), 55 VSS (power), 56 VDD (power), 57 PIO1_14 (io), 58 PIO0_18 (io), 59 PIO0_19 (io), 60 PIO0_20 (io), 61 PIO0_21 (io), 62 PIO1_15 (io), 63 PIO0_22 (io), 64 nRESET (in)

## LT1529CQ-5#PBF
designator IC?
Integrated Circuit; Manufacturer_Name: Analog Devices; Manufacturer_Part_Number: LT1529CQ-5#PBF; Description: LDO Voltage Regulators Fixed 5Vout 3A Low Dropout Regulators with Micropower Quiescent Current and Shutdown
footprint LT1529CQ5PBF
pins: 1 OUTPUT, 2 SENSE, 3 GND_1, 4 ~{SHDN}, 5 VIN, 6 GND_2

## MAX4003EUA+T
designator U?, comment Log Detect
IC LOG AMP RF DETECT 45DB 8-MSOP; Manufacturer: Maxim Integrated; Manufacturer Part Number: MAX4003EUA+T; Frequency: 100MHz ~ 2.5GHz; RF Type: Cellular, TDMA, CDMA, GPRS, GSM; Input Range: -45dBm ~ 0dBm; Voltage - Supply: 2.7 V ~ 5 V
footprint MAX4003 (µmax)
pins: 1 RFIN, 2 /SHDN, 3 GND, 4 CLPF, 5 GND, 6 NC, 7 OUT, 8 VCC

## MAX4003EUA+T_1
designator U?, comment Log Detect
IC LOG AMP RF DETECT 45DB 8-MSOP; Manufacturer: Maxim Integrated; Manufacturer Part Number: MAX4003EUA+T; Frequency: 100MHz ~ 2.5GHz; RF Type: Cellular, TDMA, CDMA, GPRS, GSM; Input Range: -45dBm ~ 0dBm; Voltage - Supply: 2.7 V ~ 5 V
footprint MAX4003 (µmax)
pins: 1 RFIN, 2 /SHDN, 3 GND, 4 CLPF, 5 GND, 6 NC, 7 OUT, 8 VCC

## mounting hole
designator PTH?
M3 mounting hole
footprint PCBComponent_1 (Footprint not found)
footprint M3-hole
pins: 1

## MS-156HF
designator J?, comment COAX JACK
CONN COAX JACK STR 50 OHM SMD; Manufacturer 1: Hirose Electric Co Ltd; Manufacturer Part Number 1: MS-156HF(01); Connector Style: Coaxial Switch - 4mm Plug Dia; Connector Type: Receptacle, Female Socket; Contact Termination: Solder; Impedance: 50 Ohm; Frequency - Max: 6GHz; Body Material: Phosphor Bronze; Body Finish: Gold; Center Contact Material: Beryllium Copper; Dielectric Material: Polyamide (PA), Nylon 6T; Coupler Type: Standard; Frequency: 700MHz ~ 1GHz; Coupling Factor: 10.9dB; Insertion Loss: 0.21dB; Power - Max: 2W; Return Loss: 17.5dB; Exact Component Match: yes
footprint MS-156HF (Subminiature Coaxial Switch)
pins: G1 GND, G2 GND, IN I, OUT O

## MS-156HF_SAW
designator J?, comment COAX JACK  Supplier Part Number 3: 490-6972-1-ND
CONN COAX JACK STR 50 OHM SMD; Manufacturer 1: Hirose Electric Co Ltd; Manufacturer Part Number 1: MS-156HF(01); Connector Style: Coaxial Switch - 4mm Plug Dia; Connector Type: Receptacle, Female Socket; Contact Termination: Solder; Impedance: 50 Ohm; Frequency - Max: 6GHz; Body Material: Phosphor Bronze; Body Finish: Gold; Center Contact Material: Beryllium Copper; Dielectric Material: Polyamide (PA), Nylon 6T; Coupler Type: Standard; Frequency: 700MHz ~ 1GHz; Coupling Factor: 10.9dB; Insertion Loss: 0.21dB; Power - Max: 2W; Return Loss: 17.5dB; Exact Component Match: yes; Capacitance: 2.2µF; Tolerance: ±20%; Voltage - Rated: 10V; Current: 4A; DC Resistance (DCR) (Max): 10 mOhm; Material - Core: Air; Shielding: Unshielded; DC Resistance (DCR): 1.25 Ohm Max
footprint MS-156HF_SAW (Coax swappable with SAW)
pins: G1 GND, G2 GND, IN I, OUT O

## NCV57302
designator U?
ADJ LDO 3A SMD D2PACK
pins: 1 EN (in), 2 VIN (power), 3 GND (power), 4 VOUT (power), 5 ADJ (in), 6 GND (power) "Thermal PAD"

## NFM18PS474R0J3D
designator C?, comment 0.47uF
CAP FEEDTHRU 0.47UF 6.3V 0603; Manufacturer: Murata Electronics North America; Manufacturer Part Number: NFM18PS474R0J3D; Capacitance: 0.47µF; Tolerance: ±20%; Current: 2A; DC Resistance (DCR) (Max): 30 mOhm; Type: Polymer; ESR (Equivalent Series Resistance): 70 mOhm; Lifetime @ Temp.: 1000 Hrs @ 105°C; Ripple Current - High Frequency: 1A @ 100kHz; Surface Mount Land Size: 0.287" L x 0.169" W (7.30mm x 4.30mm)
footprint NFM18PS (Feed Through Capacitor)
pins: 1, 2, 3

## NFM18PS474R0J3D_1
designator C?, comment 0.47uF
CAP FEEDTHRU 0.47UF 6.3V 0603; Manufacturer: Murata Electronics North America; Manufacturer Part Number: NFM18PS474R0J3D; Capacitance: 0.47µF; Tolerance: ±20%; Current: 2A; DC Resistance (DCR) (Max): 30 mOhm; Type: Polymer; ESR (Equivalent Series Resistance): 70 mOhm; Lifetime @ Temp.: 1000 Hrs @ 105°C; Ripple Current - High Frequency: 1A @ 100kHz; Surface Mount Land Size: 0.287" L x 0.169" W (7.30mm x 4.30mm)
footprint NFM18PS (Feed Through Capacitor)
pins: 1, 2, 3

## NX3225SA-20.000000MHZ-B2
designator X?, comment 20 MHZ
CRYSTAL 20.0000MHZ 7.2PF SMD; Manufacturer: NDK; Manufacturer Part Number: NX3225SA-20.000000MHZ-B2; Frequency: 20MHz; Frequency Stability: ±15ppm; Frequency Tolerance: ±10ppm; ESR (Equivalent Series Resistance): 80 Ohm; Operating Mode: Fundamental
footprint NX3225SA (20 MHz Crystal Oscillator)
pins: 1, 2 GND, 3, 4 GND

## PE64906MLAA-Z
designator U?
IC RF DTC 100-3000MHZ 10QFN; Manufacturer: Peregrine Semiconductor; Function: Digitally Tunable Capacitor; Frequency: 100MHz ~ 3GHz; RF Type: General Purpose; Secondary Attributes: SPI Interface; Exact Component Match: yes; Frequency - Lower: 500MHz; Isolation @ Frequency: 20dB @ 5.8GHz (typ); Insertion Loss @ Frequency: 0.8dB @ 5.8GHz; IIP3: 57dBm (typ); Circuit: SPDT; P1dB: 36dBm; Impedance: 50 Ohm; Voltage - Supply: 2.5 V ~ 5 V
footprint PE62304 (Digitally Tunable Capacitor for GSM/WCDMA)
pins: 1 RF_neg, 2 RF_neg, 3 GND, 4 VDD, 5 SCLK, 6 SEN, 7 SDAT, 8 RF_pos, 9 RF_pos, 10 GND

## PJ-036BH-SMT-TR
designator J
2.5 x 6.3 mm, 5.0 A, Horizontal, Surface Mount _SMT_, Dc Power Jack Connector; MP: PJ-036BH-SMT-TR; MF: CUI Devices
footprint CUI_PJ-036BH-SMT-TR
pins: 1, 2, 3

## PMBTA92
designator Q?
PNP transistor 100mA 300V; Manufacturer: On Semiconductor; PartNumber: MMBT3906LT3G; Packing: Tape and Reel; fT Min (MHz): 250; IC Continuous (A): -0.2
footprint ONSC-SOT-23-3-318-08_V (SOT23, 3-Leads, Body 2.92x1.3mm, Pitch 0.95mm)
pins: 1 B, 2 E, 3 C

## SFECF10M7EA00
designator IF?
Ceramic filter 10.7MHz
pins: 1 INPUT (in), 2 GND (power), 3 NC (hiz), 4 NC (hiz), 5 GND (power), 6 OUTPUT (out)

## SKY13431-374LF
designator S?, comment SP2T
IC SWITCH SP2T; Manufacturer: Skyworks Solutions Inc.; Manufacturer Part Number: SKY13431-374LF; Frequency - Lower: 500MHz; Isolation @ Frequency: 20dB @ 5.8GHz (typ); Insertion Loss @ Frequency: 0.8dB @ 5.8GHz; IIP3: 57dBm (typ); Circuit: SPDT; P1dB: 36dBm; Impedance: 50 Ohm; Voltage - Supply: 2.5 V ~ 5 V; RF Type: WiMax, WLAN
footprint SKY13431-374LF (6 Pin DFN)
pins: 1 V1, 2 RFC, 3 V2, 4 RF2, 5 GND, 6 RF1, 7 EP

## SSW-108-22-X-S-VS
designator J?
8Position Receptacle Connector 0.100 (2.54mm) Surface Mount Gold; MF: Samtec; MP: SSW-110-22-G-S-VS
footprint SAMTEC_SSW-110-22-X-S-VS
pins: 01, 02, 03, 04, 05, 06, 07, 08

## SSW-108-22-X-S-VS_1
designator J?
8Position Receptacle Connector 0.100 (2.54mm) Surface Mount Gold; MF: Samtec; MP: SSW-110-22-G-S-VS
footprint SAMTEC_SSW-110-22-X-S-VS
pins: 01, 02, 03, 04, 05, 06, 07, 08

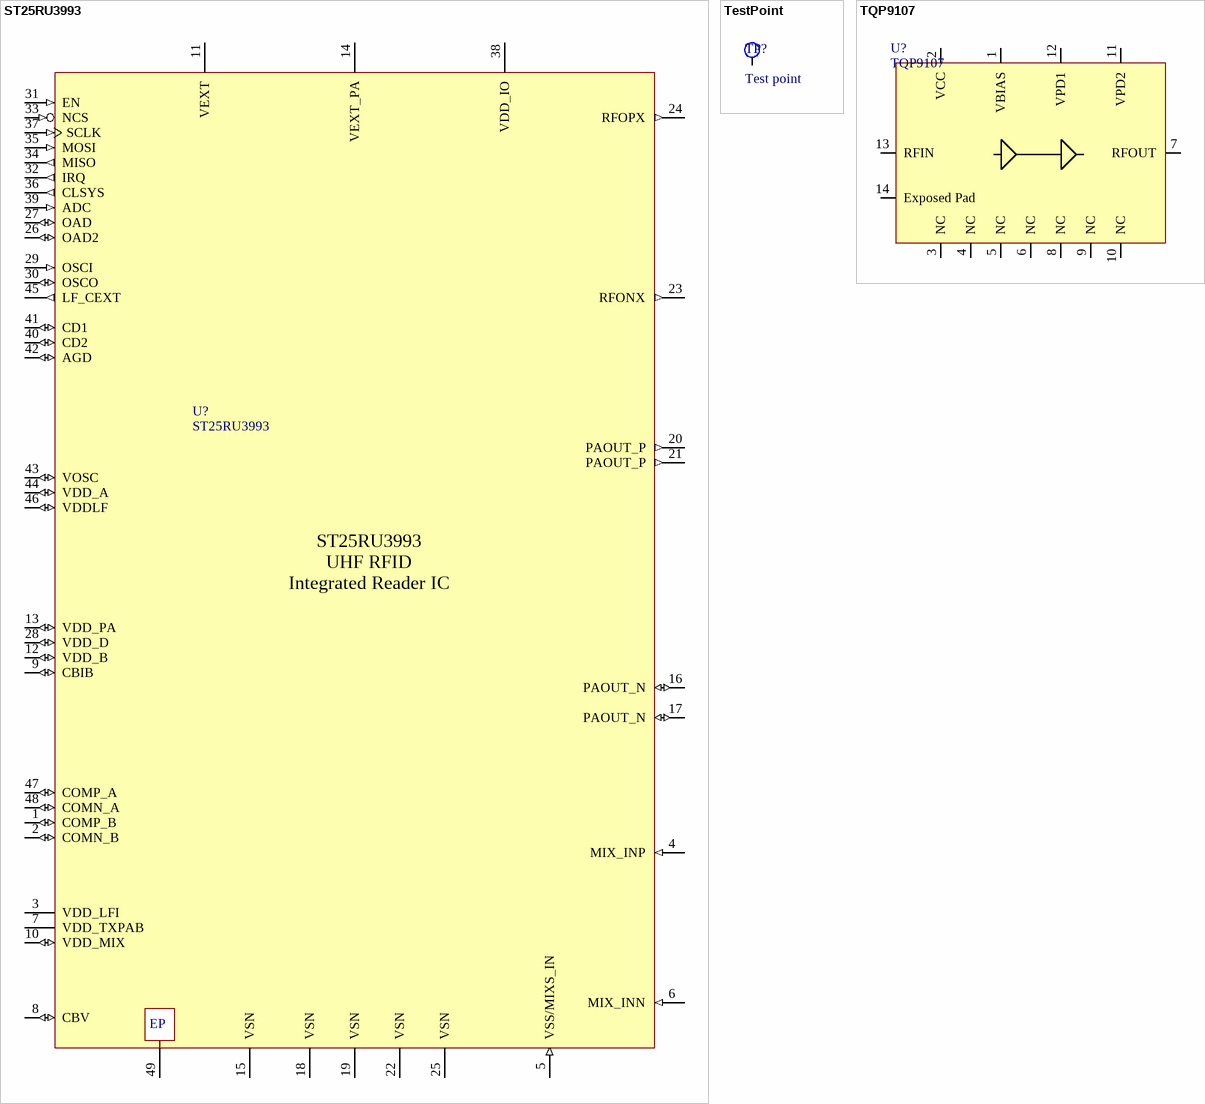
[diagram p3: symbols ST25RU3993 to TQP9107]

## ST25RU3993
designator U?
UHF EPC CLASS1 GEN2 READER; Manufacturer: ST Microelectronics; Manufacturer Part Number: AS3993-BQFT; Frequency: 860MHz ~ 960MHz; Standards: EPC, ISO 18000-6; Voltage - Supply: 2.7 V ~ 3.6 V; Exact Component Match: yes
footprint ST25RU3993_QFN48_0.5mm_pitch (QFN, 48-Leads, Body 7,0x7,0mm (max), Pitch 0,50mm, IPC Medium Density)
pins: 1 COMP_B (io), 2 COMN_B (io), 3 VDD_LFI (power), 4 MIX_INP (in), 5 VSS/MIXS_IN (in), 6 MIX_INN (in), 7 VDD_TXPAB (power), 8 CBV (io), 9 CBIB (io), 10 VDD_MIX (io), 11 VEXT (power), 12 VDD_B (io), 13 VDD_PA (io), 14 VEXT_PA (power), 15 VSN (power), 16 PAOUT_N (io), 17 PAOUT_N (io), 18 VSN (power), 19 VSN (power), 20 PAOUT_P (out), 21 PAOUT_P (out), 22 VSN (power), 23 RFONX (out), 24 RFOPX (out), 25 VSN (power), 26 OAD2 (io), 27 OAD (io), 28 VDD_D (io), 29 OSCI (in), 30 OSCO (io), 31 EN (in), 32 IRQ (out), 33 NCS (in), 34 MISO (out), 35 MOSI (in), 36 CLSYS (out), 37 SCLK (in), 38 VDD_IO (power), 39 ADC (in), 40 CD2 (io), 41 CD1 (io), 42 AGD (io), 43 VOSC (io), 44 VDD_A (io), 45 LF_CEXT (out), 46 VDDLF (io), 47 COMP_A (io), 48 COMN_A (io), 49 EP

## TestPoint
designator TP?, comment Test point
footprint PIN_DE_TEST
pins: 1 tp

## TQP9107
designator U?
699 – 960 MHz 2-stage Power Amplifier; Manufacturer: Qorvo
footprint TQP9107 (699 – 960 MHz 2-stage Power Amplifier)
pins: 1 VBIAS, 2 VCC, 3 NC, 4 NC, 5 NC, 6 NC, 7 RFOUT, 8 NC, 9 NC, 10 NC, 11 VPD2, 12 VPD1, 13 RFIN, 14 Exposed Pad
